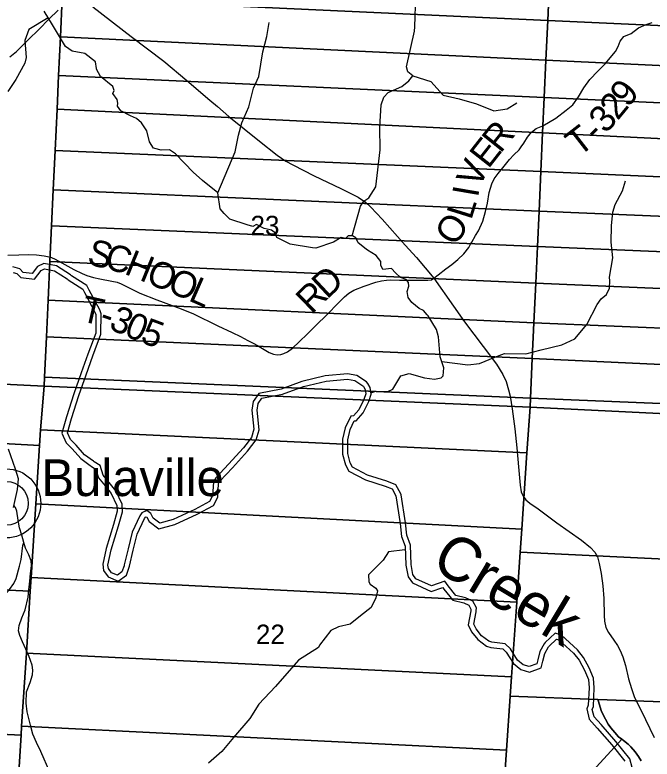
# Model space of a CAD drawing. Extents: x 1878108 to 2183446, y 146837 to 508383.
# Drawn here: x 2058800 to 2066052, y 325046 to 333510 of the extents above; entities that cross this region are included whole.
import ezdxf

# ---------------------------------------------------------------- set-up
doc = ezdxf.new("R2010")
doc.units = 0
for name, color, linetype in [('GM_X_County_Road', 7, 'Continuous'), ('GM_X_Minor_River', 7, 'Continuous'), ('GM_X_Minor_River_Text', 7, 'Continuous'), ('GM_X_Section', 7, 'Continuous'), ('GM_X_Section_Text', 7, 'Continuous'), ('GM_X_Township_Road', 7, 'Continuous'), ('GM_X_Township_Road_Text', 7, 'Continuous'), ('GM_X_Unincorporated', 7, 'Continuous'), ('GM_X_Unincorporated_Text', 7, 'Continuous')]:
    doc.layers.add(name, color=color, linetype=linetype)

msp = doc.modelspace()

# ---------------------------------------------------------------- linework, layer by layer
at = {"layer": 'GM_X_County_Road'}
for points in [[(2058743.6, 333034.3), (2058817, 333091.9), (2058952.4, 333227.3), (2059076.3, 333348.3), (2059187.2, 333459.2), (2059292.3, 333561.4)], [(2059688.4, 333600.3), (2060124.7, 333263.3), (2060494.9, 332982.5), (2060757, 332765), (2061020.4, 332538.2), (2061105.5, 332468.3), (2061235.1, 332353.1), (2061583.7, 332072.3), (2061785.3, 331915.3), (2061884.7, 331844.7), (2061962.4, 331804.4), (2062207.3, 331679.1), (2062509.7, 331535.1), (2062707, 331437.1), (2062790.6, 331381), (2062852.5, 331323.3), (2062980.7, 331186.5), (2063242.8, 330889.8), (2063372.4, 330748.7), (2063569.2, 330515), (2063790.8, 330197.1), (2063915.6, 330019), (2064128.2, 329738.1), (2064280.9, 329536), (2064354.7, 329421.1), (2064389.9, 329341.6), (2064419.3, 329244.6), (2064436.4, 329173.7), (2064460.2, 329028.5), (2064489.7, 328801.6), (2064513.5, 328586), (2064531.7, 328368.1), (2064549.9, 328162.8), (2064563.5, 328086.7), (2064585, 328038), (2064615.7, 327996), (2064662.2, 327958.5), (2064754.1, 327890.5), (2064969.7, 327732.7), (2065247.6, 327535.3), (2065352, 327451.4), (2065399.7, 327400.3), (2065430.3, 327345.8), (2065450.7, 327272.1), (2065472.3, 327156.4), (2065490.2, 327015.2), (2065504.5, 326872.4), (2065507.1, 326679.1), (2065512.3, 326612.9), (2065525.2, 326544.1), (2065555.1, 326485.7), (2065617.4, 326397.4), (2065657.6, 326339), (2065688.8, 326280.6), (2065717.3, 326210.6), (2065748.5, 326109.3), (2065785.2, 325957.8), (2065817.2, 325849.8), (2065848.4, 325756.3), (2065976.9, 325496.8), (2066075.5, 325291.7)], [(2059198.1, 324899.2), (2059096.3, 325131.6), (2059045.4, 325236.1), (2059004.1, 325331), (2058978, 325431.5), (2058939.5, 325582.8), (2058928.5, 325683.2), (2058934, 325811.1), (2058972.5, 325918.4), (2059001.4, 326005), (2059005.5, 326058.7), (2058998.6, 326115.1), (2058960.1, 326222.3), (2058888.6, 326380.5), (2058856.9, 326450.7), (2058843.2, 326502.9), (2058847.3, 326564.8), (2058880.3, 326654.2), (2058916.1, 326745), (2058951.9, 326886.7), (2058960.1, 326970.6), (2058969.7, 327071), (2058979.4, 327154.9), (2058989, 327247.1), (2058984.9, 327300.7), (2058957.4, 327368.1), (2058923, 327446.7), (2058903.7, 327511.1), (2058879, 327593.2), (2058852.9, 327674.9), (2058835.9, 327762.2), (2058822.3, 327866.6), (2058806.4, 327907.5), (2058788.2, 327929)]]:
    msp.add_lwpolyline(points, dxfattribs=at)
at = {"layer": 'GM_X_Minor_River'}
for points in [[(2062637.1, 330997.4), (2062734.6, 331333.5), (2062770.9, 331391.5), (2062827.1, 331429.5), (2062909.8, 331553.6), (2062955.7, 331975.1), (2062952.7, 332232.1), (2062969.8, 332485.1), (2063000.3, 332575.3), (2063048.6, 332627.3), (2063205.1, 332696.9), (2063283.5, 332760.8), (2063327.8, 332814.8), (2063273.9, 332861.2), (2063256.1, 332917.5), (2063348, 333322.7), (2063350.2, 333372.9), (2063363.7, 333734.3), (2063394.1, 333794.4), (2063549, 333970.4), (2063641.6, 334064.4), (2063780.7, 334282.6), (2063815.2, 334374.8)], [(2059180.3, 333476.1), (2058960.2, 333342.4), (2058913.6, 333217.5), (2058928, 333023.1), (2058912.7, 332960.8), (2058812.8, 332773.1), (2058718.3, 332639.6)], [(2062852.9, 329212.3), (2062909.2, 329231.3), (2063045.1, 329227.9), (2063102.9, 329254.3), (2063192, 329403), (2063287.7, 329429.5), (2063461.7, 329382.3), (2063575.7, 329366.8), (2063651.5, 329381.2), (2063675.3, 329403.4), (2063680.9, 329495.6), (2063640.3, 329619.7), (2063621.2, 329850.1), (2063596.8, 329932.1), (2063502.2, 330086), (2063494.1, 330097.9), (2063450, 330147.8), (2063399.9, 330169.6), (2063319.7, 330237.4), (2063275.5, 330295.3), (2063263.1, 330363.3), (2063282.8, 330425.6), (2063278.6, 330467.6), (2063254.5, 330501.6), (2063188.5, 330523.3), (2063130.3, 330577.1), (2063088.1, 330627), (2062986.3, 330614.5), (2062964.1, 330662.5), (2062965.9, 330704.6), (2062913.6, 330772.5), (2062813.4, 330834.1), (2062797.4, 330846), (2062707.2, 330915.7), (2062678.9, 330973.7), (2062640.9, 330997.6), (2062594.9, 330995.3), (2062561.1, 330967.1), (2062513.1, 330976.9), (2062425.5, 330924.4), (2062224.1, 330857.2), (2062188.2, 330859), (2061934.3, 330901.9), (2061780.1, 330979.3), (2061767.9, 331027.3), (2061719.8, 331061.1), (2061705.8, 331065.1), (2061635.8, 331078.8), (2061551.7, 331124.4), (2061507.9, 331102.2), (2061443.9, 331121.9), (2061245.8, 331187), (2061181.6, 331250.8), (2061135.4, 331304.7), (2061110.7, 331485.3), (2060936.1, 331624.4), (2060827.8, 331720), (2060627, 331929.5), (2060558.9, 331973.2), (2060465, 331972.7), (2060393, 331990.4), (2060379, 331994.3), (2060330.8, 332064.2), (2060302.2, 332192.4), (2060239.8, 332282.2), (2060185.7, 332330), (2060117.6, 332359.8), (2060007.5, 332417.3), (2059969.2, 332473.3), (2059971.1, 332507.3), (2059964.9, 332545.4), (2059914.6, 332617.3), (2059928.4, 332651.4), (2059916.2, 332695.5), (2059773.9, 332809), (2059729.5, 332890.9), (2059727.5, 332900.9), (2059719.1, 332975), (2059596.8, 333070.6), (2059450.9, 333097.9), (2059376.7, 333151.7), (2059229.7, 333397.4), (2059133.1, 333551.2)], [(2061110.7, 331485.3), (2061309, 331952.3), (2061345.8, 332140.9), (2061384.5, 332283.3), (2061463.4, 332465.7), (2061514.4, 332676.3), (2061575, 332808.5), (2061620.3, 333087.5), (2061669.1, 333261.9), (2061693.8, 333422.5)], [(2063327.8, 332814.8), (2063533.9, 332753.6), (2063673.4, 332598.4), (2063857.5, 332555.4), (2064053.6, 332498.3), (2064251.6, 332419.1), (2064401.9, 332442.5), (2064512.4, 332510.3)], [(2063657.7, 329566.5), (2063954.9, 329530.7), (2064089.2, 329544.2), (2064263.8, 329617.7), (2064372.1, 329659.4), (2064616.5, 329654.2), (2064789, 329701.7), (2065023.6, 329756.8), (2065172.1, 329826.5), (2065309, 329988.5), (2065428.2, 330216.9), (2065472.5, 330281), (2065532.8, 330328.9), (2065567.2, 330403), (2065569.5, 330483.3), (2065567.7, 330527.5), (2065606.7, 330746.2), (2065587.4, 330925.1), (2065590.2, 331111.8), (2065604.9, 331266.4), (2065633.3, 331352.6), (2065716.1, 331506.8), (2065750.6, 331621.2)], [(2059859.2, 327250), (2059896.3, 327424.6), (2059980.9, 327697.6), (2060024, 327858.1), (2060019.6, 327944.3), (2059948.9, 328098.2), (2059874.6, 328192.1), (2059804.3, 328273.9), (2059769.8, 328383.9), (2059703.6, 328425.7), (2059693.6, 328433.7), (2059591.4, 328507.3), (2059497, 328617.1), (2059434.8, 328678.9), (2059398.4, 328756.8), (2059445.6, 328921.4), (2059528.2, 329180.4), (2059610.9, 329417.3), (2059687.7, 329632.1), (2059780.4, 329877.1), (2059781.2, 330111.5), (2059767, 330153.6), (2059646.1, 330379.4), (2059617.8, 330431.4), (2059445.5, 330542.8), (2059433.5, 330554.7), (2059273.2, 330656.1), (2059129.3, 330683.5), (2059059.6, 330649), (2058996, 330568.6), (2058896.1, 330580.1), (2058856, 330620), (2058778, 330645.6)], [(2058780.7, 330581.6), (2058823.8, 330567.4), (2058868.6, 330522.9), (2059022.4, 330505.1), (2059098.2, 330601.2), (2059137.8, 330620.8), (2059250.8, 330599.3), (2059395.9, 330507.5), (2059407.7, 330495.8), (2059572.4, 330389.3), (2059593.3, 330350.9), (2059711.8, 330129.6), (2059721.2, 330101.8), (2059720.4, 329888.1), (2059631.4, 329652.8), (2059554.3, 329437.3), (2059471.3, 329199.4), (2059388.1, 328938.8), (2059334.6, 328751.8), (2059384.9, 328643.8), (2059453, 328576.1), (2059550.6, 328462.8), (2059657.4, 328385.8), (2059668.9, 328376.7), (2059719.1, 328345), (2059750.7, 328244.1), (2059828.3, 328153.8), (2059897.4, 328066.6), (2059960.3, 327929.7), (2059963.6, 327864.5), (2059923.2, 327714.2), (2059838.2, 327439.7), (2059800.6, 327262.5)], [(2065853, 324852.5), (2065798.1, 325048.7), (2065639.3, 325246.3), (2065472.6, 325437.9), (2065392.3, 325527.7), (2065371.9, 325611.8), (2065385.7, 325645.9), (2065394.6, 325856.4), (2065386.1, 325964.6), (2065335.6, 326082.6), (2065273.1, 326202.5), (2065202.7, 326290.4), (2065020.2, 326455.8), (2064950.1, 326477.5), (2064836.8, 326372.8), (2064824.9, 326358.7), (2064775.4, 326268.3), (2064751.9, 326173.9), (2064740.2, 326129.8), (2064654.4, 326097.3), (2064586.4, 326119), (2064520.2, 326172.8), (2064439.7, 326298.7), (2064379.5, 326358.5), (2064229.6, 326375.8), (2064193.6, 326385.6), (2064111.4, 326449.4), (2064049.1, 326527.2), (2064022.9, 326581.2), (2064048.1, 326721.6), (2064050.1, 326733.7), (2064051.9, 326765.8), (2064011.6, 326843.7), (2063929.5, 326881.4), (2063817.5, 326906.9), (2063731.1, 327014.7), (2063692.9, 327068.6), (2063541.3, 327017.8), (2063365.2, 327097.1), (2063331, 327145), (2063308.5, 327259.1), (2063301.4, 327477.6), (2063260.9, 327591.6), (2063246.2, 327733.8), (2063194.7, 328052.2), (2063192.6, 328062.2), (2063134.2, 328166.2), (2063034.1, 328205.8), (2062814.1, 328276.8), (2062643.9, 328364.2), (2062617.7, 328414.1), (2062589.2, 328522.2), (2062590.4, 328676.5), (2062615.8, 328792.9), (2062663.2, 328891.3), (2062683.2, 328893.5), (2062764.7, 328984), (2062827.9, 329112.6), (2062855.5, 329196.9), (2062843.1, 329271), (2062816.9, 329317), (2062800.9, 329337), (2062692.6, 329408.6), (2062586.7, 329428.1), (2062331.2, 329404.8), (2062065.8, 329339.3), (2061830.6, 329254), (2061577.2, 329204.6), (2061511.7, 329112.1), (2061496.2, 329015.8), (2061519.3, 328797.5), (2061491.8, 328705.2), (2061402.5, 328586.5), (2061231.6, 328399.2), (2061086.6, 328244.2), (2061078.7, 328234.1), (2061058.9, 328196), (2061049.7, 328039.6), (2061016, 327975.3), (2060846.7, 327886.3), (2060601.6, 327770.8), (2060450, 327730), (2060375.9, 327787.7), (2060347.6, 327837.7), (2060303.5, 327873.5), (2060245.8, 327845.2), (2060224, 327811), (2060135, 327626.2), (2060090, 327437.6), (2060045, 327255), (2060043, 327244.9), (2060019.4, 327176.7), (2059967.6, 327138.3), (2059901.6, 327166.1), (2059865.4, 327214), (2059859.2, 327250)], [(2059800.6, 327262.5), (2059808.7, 327189.5), (2059863.5, 327117), (2059975.9, 327069.8), (2060070, 327139.5), (2060101.1, 327229.3), (2060103.6, 327242), (2060148.3, 327423.4), (2060191.8, 327606), (2060276.5, 327781.8), (2060287.3, 327798.7), (2060295.5, 327802.8), (2060301, 327798.3), (2060329.5, 327747.8), (2060436.8, 327664.2), (2060622.4, 327714.3), (2060873.5, 327832.5), (2061060.5, 327930.9), (2061108.8, 328023.2), (2061118, 328179.7), (2061129.3, 328201.5), (2061132.2, 328205), (2061275.7, 328358.5), (2061448.7, 328548.1), (2061546.2, 328677.7), (2061580.2, 328791.9), (2061556.7, 329014.2), (2061568.7, 329088.8), (2061612.3, 329150.3), (2061846.6, 329196), (2062083.3, 329281.8), (2062341.1, 329345.4), (2062583.9, 329367.6), (2062669.7, 329351.8), (2062760, 329292), (2062767.2, 329283.1), (2062785.7, 329250.6), (2062793.9, 329201.6), (2062772.2, 329135.3), (2062714.5, 329018), (2062654, 328950.7), (2062623.7, 328947.5), (2062558.7, 328812.6), (2062530.5, 328683.2), (2062529.1, 328514.7), (2062561.4, 328392.3), (2062599.6, 328319.4), (2062791, 328221.2), (2063013.9, 328149.2), (2063092.3, 328118.2), (2063135.7, 328041), (2063186.7, 327725.9), (2063201.9, 327578.3), (2063241.7, 327466.3), (2063248.7, 327252.3), (2063274.6, 327120.7), (2063325.8, 327049), (2063538.1, 326953.4), (2063669.7, 326997.5), (2063683.2, 326978.5), (2063783.8, 326853), (2063910.1, 326824.3), (2063967.8, 326797.8), (2063991.1, 326752.8), (2063990.3, 326740.2), (2063989, 326731.7), (2063960.3, 326572.6), (2063998.1, 326495), (2064069, 326406.3), (2064166.3, 326330.9), (2064218.2, 326316.7), (2064352, 326301.3), (2064392.7, 326260.8), (2064474.9, 326132.3), (2064557.4, 326065.3), (2064656.1, 326033.8), (2064790.2, 326084.6), (2064810, 326159), (2064831.8, 326246.2), (2064874.6, 326324.6), (2064880.2, 326331.2), (2064965.5, 326410), (2064989.7, 326402.5), (2065158.9, 326249.1), (2065222.6, 326169.6), (2065281.3, 326056.9), (2065327.1, 325950.1), (2065334.5, 325855.3), (2065326.2, 325658.8), (2065309, 325616.4), (2065337.5, 325498.9), (2065427.6, 325398.2), (2065593.3, 325207.8), (2065743.7, 325020.7)], [(2058783.4, 327907.7), (2058829.9, 328111), (2058840.7, 328232.6), (2058808.6, 328343.4), (2058725.9, 328570.4)], [(2063238, 327425.3), (2063050.5, 327402.1), (2062990, 327310), (2062823, 327142), (2062826.7, 327063.7), (2062842.6, 327035.5), (2062908.5, 326991), (2062928.4, 326958.8), (2062908.1, 326878.6), (2062853.5, 326770.4), (2062734.9, 326674.5), (2062614.3, 326580.6), (2062482, 326551.1), (2062395.7, 326507.3), (2062268.8, 326343.2), (2062256.7, 326315.2), (2062027.7, 326169.6), (2061768, 325871.5), (2061576.9, 325669.6), (2061474, 325509.4), (2061288.8, 325293.3), (2061155.9, 325131.2), (2061003.1, 324999.4)]]:
    msp.add_lwpolyline(points, dxfattribs=at)
at = {"layer": 'GM_X_Section'}
for points in [[(2054013.5, 334822), (2059379.9, 334594.7), (2059359.2, 334147.8), (2059338.6, 333704.8), (2059318.1, 333260.5), (2059297.7, 332821.6), (2059280, 332439), (2059258.2, 331968), (2059237.5, 331520.9), (2059218.5, 331111.7), (2059199.6, 330704.8), (2059179.3, 330265.7), (2059160, 329849.8), (2059138.7, 329390.8), (2059134, 329288.4), (2053667.7, 329555.5)], [(2064884.4, 333898.6), (2064863.8, 333444.9), (2059338.6, 333704.8), (2059359.2, 334147.8)], [(2070481.3, 333638.4), (2070447.8, 333192), (2064863.8, 333444.9), (2064884.4, 333898.6)], [(2059338.6, 333704.8), (2064863.8, 333444.9), (2064843.3, 332994), (2059318.1, 333260.5)], [(2064863.8, 333444.9), (2070447.8, 333192), (2070413.4, 332733.4), (2064843.3, 332994)], [(2064843.3, 332994), (2064824, 332571), (2059297.7, 332821.6), (2059318.1, 333260.5)], [(2070413.4, 332733.4), (2070381.9, 332315.1), (2064824, 332571), (2064843.3, 332994)], [(2059297.7, 332821.6), (2064824, 332571), (2064805.7, 332168.3), (2059280, 332439)], [(2064824, 332571), (2070381.9, 332315.1), (2070350.3, 331894.1), (2064805.7, 332168.3)], [(2064805.7, 332168.3), (2064785.7, 331728), (2059258.2, 331968), (2059280, 332439)], [(2070350.3, 331894.1), (2070319.4, 331482.6), (2064785.7, 331728), (2064805.7, 332168.3)], [(2059258.2, 331968), (2064785.7, 331728), (2064765.1, 331275.8), (2059237.5, 331520.9)], [(2064785.7, 331728), (2070319.4, 331482.6), (2070286.4, 331044.3), (2064765.1, 331275.8)], [(2064765.1, 331275.8), (2064747, 330877), (2059218.5, 331111.7), (2059237.5, 331520.9)], [(2070286.4, 331044.3), (2070256.5, 330646.1), (2064747, 330877), (2064765.1, 331275.8)], [(2059218.5, 331111.7), (2064747, 330877), (2064727.9, 330456.8), (2059199.6, 330704.8)], [(2064747, 330877), (2070256.5, 330646.1), (2070224.9, 330225), (2064727.9, 330456.8)], [(2064727.9, 330456.8), (2064707.5, 330008.5), (2059179.3, 330265.7), (2059199.6, 330704.8)], [(2070224.9, 330225), (2070191.3, 329778.4), (2064707.5, 330008.5), (2064727.9, 330456.8)], [(2059179.3, 330265.7), (2064707.5, 330008.5), (2064689, 329601.6), (2059160, 329849.8)], [(2064707.5, 330008.5), (2070191.3, 329778.4), (2070159, 329348.3), (2064689, 329601.6)], [(2064689, 329601.6), (2064668.5, 329151.9), (2059138.7, 329390.8), (2059160, 329849.8)], [(2070159, 329348.3), (2070127.4, 328928.3), (2064668.5, 329151.9), (2064689, 329601.6)], [(2059134, 329288.4), (2059092.8, 328791.3), (2059081.4, 328612.2), (2056381.3, 328758.4), (2053629.4, 328907.5), (2053667.7, 329555.5)], [(2059138.7, 329390.8), (2064668.5, 329151.9), (2064663.7, 329046.6), (2059134, 329288.4)], [(2064663.7, 329046.6), (2064627.9, 328527.2), (2059092.8, 328791.3), (2059134, 329288.4)], [(2064668.5, 329151.9), (2070127.4, 328928.3), (2070116.6, 328784.5), (2067471.6, 328911.6), (2066291.8, 328968.3), (2064663.7, 329046.6)], [(2066291.8, 328968.3), (2066246.2, 328151.3), (2066218.4, 327653.8), (2066199.6, 327318.8), (2064550.4, 327401.1), (2064568.4, 327662.1), (2064627.9, 328527.2), (2064663.7, 329046.6)], [(2059081.4, 328612.2), (2059039, 327949.1), (2058985.4, 327109.6), (2058975.7, 326957.6), (2056276, 327082.6), (2056381.3, 328758.4)], [(2059092.8, 328791.3), (2064627.9, 328527.2), (2064568.4, 327662.1), (2059039, 327949.1), (2059081.4, 328612.2)], [(2059039, 327949.1), (2064568.4, 327662.1), (2064550.4, 327401.1), (2064511.2, 326832.1), (2058985.4, 327109.6)], [(2064550.4, 327401.1), (2066199.6, 327318.8), (2067226.6, 327267.6), (2067149.7, 326172.6), (2067113.9, 325661.7), (2065434.1, 325724.1), (2064437.4, 325761.1), (2064452.7, 325982.2), (2064511.2, 326832.1)], [(2058975.7, 326957.6), (2058930.7, 326252.6), (2058877.5, 325419.7), (2058870.9, 325317.3), (2056173.4, 325449.1), (2056276, 327082.6)], [(2058985.4, 327109.6), (2064511.2, 326832.1), (2064452.7, 325982.2), (2058930.7, 326252.6), (2058975.7, 326957.6)], [(2058930.7, 326252.6), (2064452.7, 325982.2), (2064437.4, 325761.1), (2064395.2, 325148.1), (2058877.5, 325419.7)], [(2065434.1, 325724.1), (2065442.7, 325700.2), (2065471.7, 325598.6), (2065495.1, 325549.2), (2065521.2, 325499.7), (2065553.6, 325444.3), (2065582.9, 325402.7), (2065629, 325349.1), (2065671.3, 325299.8), (2065707.4, 325271.6), (2065296.1, 324821.3), (2064380.2, 324929.7), (2064395.2, 325148.1), (2064437.4, 325761.1)], [(2058870.9, 325317.3), (2058824.7, 324593.8), (2058787.9, 324017.1), (2056092.1, 324137.5), (2056173.4, 325449.1)], [(2058877.5, 325419.7), (2064395.2, 325148.1), (2064380.2, 324929.7), (2064339.8, 324343.8), (2058824.7, 324593.8), (2058870.9, 325317.3)]]:
    msp.add_lwpolyline(points, close=True, dxfattribs=at)
for points in [[(2065928, 325025.9), (2065896.5, 325075.8), (2065858.6, 325130.2), (2065811.4, 325185.3), (2065778.6, 325217.5), (2065724.9, 325258), (2065707.4, 325271.6), (2065671.3, 325299.8), (2065629, 325349.1), (2065582.9, 325402.7), (2065553.6, 325444.3), (2065521.2, 325499.7), (2065495.1, 325549.2), (2065471.7, 325598.6), (2065442.7, 325700.2), (2065434.1, 325724.1), (2067113.9, 325661.7), (2067070.4, 325041.7)], [(2065296.1, 324821.3), (2065707.4, 325271.6), (2065724.9, 325258), (2065778.6, 325217.5), (2065811.4, 325185.3), (2065858.6, 325130.2), (2065896.5, 325075.8), (2065928, 325025.9)]]:
    msp.add_lwpolyline(points, dxfattribs=at)
at = {"layer": 'GM_X_Township_Road'}
for points in [[(2064562.1, 332008.9), (2064590.8, 332049.2), (2064632.6, 332119.8), (2064681.5, 332177.4), (2064733.4, 332219.2), (2064809.7, 332249.4), (2064955.1, 332334.9), (2065075, 332427.5), (2065148.2, 332488.5), (2065212.8, 332578.2), (2065274.9, 332680), (2065344, 332775.1), (2065433.3, 332870.1), (2065522.6, 332955.1), (2065575.9, 333022.8), (2065635, 333093.4), (2065666.6, 333149.5), (2065689.7, 333211.5), (2065730, 333261.9), (2065813.5, 333297.9), (2065897.1, 333361.2), (2065983.5, 333398.7), (2066052.6, 333423.2)], [(2064042.4, 330999.6), (2064075.2, 331055.5), (2064124.2, 331162), (2064157.3, 331272.9), (2064180.3, 331369.4), (2064199.1, 331489), (2064227.9, 331589.8), (2064256.7, 331646), (2064301.3, 331706.4), (2064354.6, 331768.4), (2064430.9, 331863.4), (2064478.5, 331916.7), (2064537.5, 331974.3), (2064562.1, 332008.9)], [(2063989.5, 330908.3), (2063999.6, 330926.7), (2064042.4, 330999.6)], [(2063569.2, 330515), (2063616.1, 330552.3), (2063705.7, 330622.6), (2063771.5, 330672.6), (2063841.8, 330729.3), (2063909.6, 330793.4), (2063965.5, 330864.3), (2063989.5, 330908.3)], [(2058719, 330775.8), (2058845, 330781.5), (2058960.7, 330784.9), (2059044.7, 330779.2), (2059132, 330767.9), (2059172.9, 330762.2), (2059216, 330748.6), (2059258, 330730.4), (2059370.3, 330672.6), (2059472.4, 330615.8), (2059567.7, 330567), (2059618.8, 330545.5), (2059695.9, 330522.8), (2059768.5, 330508), (2059904.7, 330481.9), (2059964.8, 330468.3), (2060009.1, 330451.3), (2060078.3, 330415), (2060223.5, 330345.8), (2060414.1, 330267.5), (2060694.4, 330166.5), (2060831.7, 330108.6), (2061110.8, 329974.8), (2061271.9, 329898.7), (2061367.2, 329852.2), (2061451.2, 329808), (2061518.1, 329773.9), (2061560.1, 329749), (2061597.6, 329727.4), (2061637.3, 329704.7), (2061694, 329670.7), (2061742.8, 329650.3), (2061785.9, 329644.6), (2061826.8, 329648), (2061860.8, 329657.1), (2061901.6, 329678.6), (2061960.6, 329719.5), (2062035.5, 329790.9), (2062130.8, 329882.9), (2062222.7, 329974.8), (2062356.6, 330106.4), (2062475.8, 330225.5), (2062550.6, 330301.5), (2062599.4, 330344.6), (2062656.2, 330378.7), (2062776.4, 330426.3), (2062908, 330469.5), (2062973.9, 330486.5), (2063029.5, 330494.4), (2063079.4, 330496.7), (2063177, 330493.3), (2063284.7, 330492.1), (2063407.7, 330492), (2063501.5, 330491), (2063543.4, 330495.6), (2063569.2, 330515)], [(2057633.7, 325705.2), (2057687.8, 325761.6), (2057835, 325929.4), (2058068.8, 326201.7), (2058233.8, 326404.8), (2058328.8, 326507.1), (2058444.3, 326628.1), (2058489.7, 326684.5), (2058602.5, 326822), (2058649.3, 326872.9), (2058737.3, 326973.3), (2058788.2, 327042.1), (2058814.3, 327101.3), (2058854.5, 327238.7), (2058870.4, 327315), (2058892.7, 327476.8), (2058903.7, 327511.1)]]:
    msp.add_lwpolyline(points, dxfattribs=at)
at = {"layer": 'GM_X_Unincorporated'}
for radius in [392.8, 249]:
    msp.add_circle((2058702.6, 327954.4), radius, dxfattribs=at)

# ---------------------------------------------------------------- texts
at = {"layer": 'GM_X_Minor_River_Text'}
msp.add_text('Creek', height=500.01, rotation=328.99806, dxfattribs=at).set_placement((2063518.8, 327232.2))
at = {"layer": 'GM_X_Section_Text'}
for s, p in [('23', (2061482.3, 331003.8)), ('22', (2061543.9, 326354.7))]:
    msp.add_text(s, height=221, rotation=0.00001, dxfattribs=at).set_placement(p)
at = {"layer": 'GM_X_Township_Road_Text'}
for s, rotation, p in [('9', 51.4452, (2065780.6, 332446.6)), ('2', 50.63571, (2065660.4, 332300.1)), ('3', 47.48134, (2065523.8, 332150.3)), ('R', 51.40785, (2064326.6, 331926.6)), ('T', 37.85393, (2065218, 331889.4)), ('-', 44.25236, (2065422.7, 332051.1)), ('E', 51.90174, (2064188.5, 331750.6)), ('V', 64.7188, (2064085.1, 331526.9)), ('I', 80.41491, (2064071.1, 331426.1)), ('L', 72.57664, (2063993.4, 331168.5)), ('O', 57.10609, (2063812.5, 330867)), ('S', 345.80012, (2059610.4, 330677.9)), ('C', 345.13546, (2059805.8, 330628.5)), ('H', 337.75956, (2060034.2, 330568.6)), ('O', 337.36248, (2060278.1, 330468.9)), ('O', 337.25629, (2060521.6, 330367.3)), ('D', 43.01885, (2062352.4, 330268.9)), ('L', 336.27075, (2060763.8, 330265.8)), ('R', 44.5529, (2062178.3, 330097.5)), ('T', 347.28805, (2059536.3, 330029.4)), ('3', 336.2568, (2059856.9, 329943.8)), ('-', 340.58508, (2059746.3, 329982.6)), ('0', 337.12651, (2060030.7, 329867.5)), ('5', 339.91251, (2060215.7, 329789.8))]:
    msp.add_text(s, height=300, rotation=rotation, dxfattribs=at).set_placement(p)
at = {"layer": 'GM_X_Unincorporated_Text'}
msp.add_text('Bulaville', height=417, rotation=0.00001, dxfattribs=at).set_placement((2059101.9, 328037.7))

doc.saveas('drawing.dxf')
